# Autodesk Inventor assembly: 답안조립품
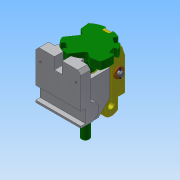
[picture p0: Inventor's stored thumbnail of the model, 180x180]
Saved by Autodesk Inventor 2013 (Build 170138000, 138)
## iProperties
Created: 2016-11
Part Number: 답안조립품
Document SubType Name: Assembly
Designer: Administrator
Author: Administrator
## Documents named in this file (8)
- C:\Users\Administrator\Desktop\461108V1006\답안조립품.iam
- C:\Users\Administrator\Desktop\461108V1006\본체.ipt
- C:\Users\Administrator\Desktop\461108V1006\부시.ipt
- C:\Users\Administrator\Desktop\461108V1006\분할대.ipt
- C:\Users\Administrator\Desktop\461108V1006\분할축.ipt
- C:\Users\Administrator\Desktop\461108V1006\와셔.ipt
- C:\Users\Administrator\Desktop\461108V1006\원통형핀.ipt
- C:\Users\Administrator\Desktop\461108V1006\클레비스핀.ipt
